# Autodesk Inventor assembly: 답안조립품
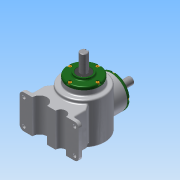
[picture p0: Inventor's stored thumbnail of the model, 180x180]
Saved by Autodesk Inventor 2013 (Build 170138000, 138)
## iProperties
Created: 2018-08
Part Number: 답안조립품
Document SubType Name: Assembly
Designer: Administrator
Author: Administrator
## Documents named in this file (15)
- C:\Users\Administrator\Desktop\480808V1015\480808V1015\답안조립품.iam
- C:\Users\Administrator\Desktop\480808V1015\480808V1015\본체.ipt
- C:\Users\Administrator\Desktop\480808V1015\480808V1015\메인 베벨기어.ipt
- C:\Users\Administrator\Desktop\480808V1015\480808V1015\메인 축.ipt
- 메인 축.ipt
- C:\Users\Administrator\Desktop\480808V1015\480808V1015\베어링 6203.ipt
- C:\Users\Administrator\Desktop\480808V1015\480808V1015\볼트 M4.ipt
- C:\Users\Administrator\Desktop\480808V1015\480808V1015\서브 베벨기어.ipt
- C:\Users\Administrator\Desktop\480808V1015\480808V1015\서브 축.ipt
- 서브 축.ipt
- C:\Users\Administrator\Desktop\480808V1015\480808V1015\오일실 17 32 8.ipt
- C:\Users\Administrator\Desktop\480808V1015\480808V1015\커버.ipt
- C:\Users\Administrator\Desktop\480808V1015\480808V1015\키 4x4.ipt
- C:\Users\Administrator\Desktop\480808V1015\480808V1015\키 5x5.ipt
- C:\Users\Administrator\Desktop\480808V1015\480808V1015\커버_CPY.ipt
